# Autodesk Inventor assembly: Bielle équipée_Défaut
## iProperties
Shininess: 64.0
Length Units: 11269
Angle Units: 11279
Time Units: 11290
Mass Units: 11283
Length Display Precision: 3
Angle Display Precision: 2
Compacted: True
Created: 2006-01
Part Number: Bielle équipée_Défaut
Document SubType Name: Assembly
Designer: riri
Density: 0.0
Volumn: 0.0
Area: 0.0
PropertySet Name: Model Information
Control State: 0
Master: False
Checked Out: False
Author: riri
